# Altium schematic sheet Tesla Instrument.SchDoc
size A4
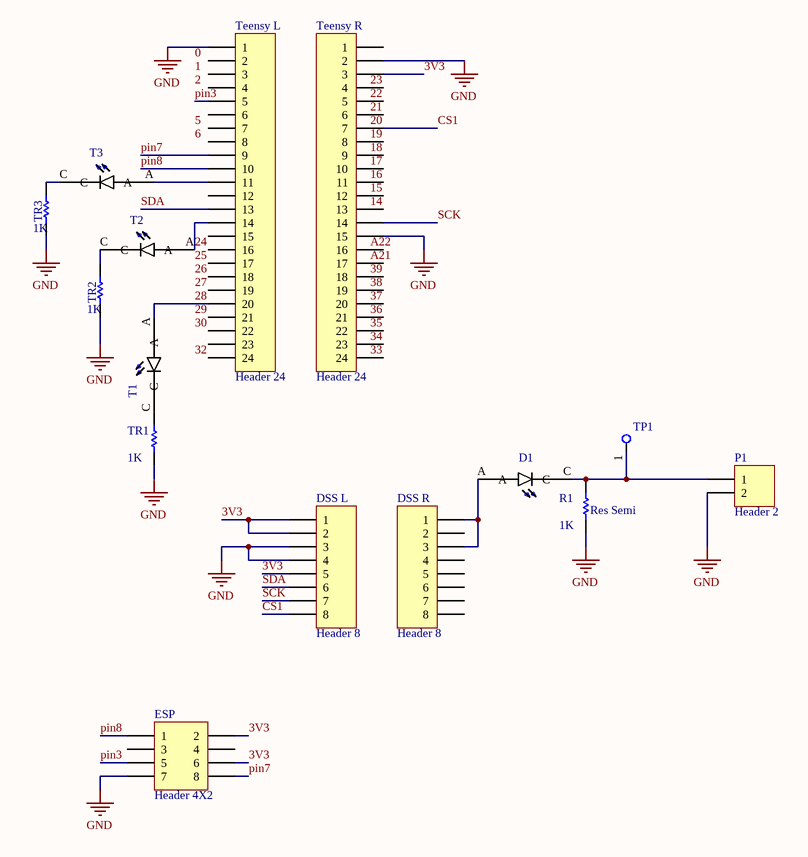
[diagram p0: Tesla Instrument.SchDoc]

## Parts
D1  LTL-1CHYE  [LED_LTL-1CHYE_LTL-1CHYE(Primary)]  (value not drawn)
DSS_L  Header 8  [HDR1X8]
DSS_R  Header 8  [HDR1X8]
ESP  Header 4X2  [HDR2X4]
P1  Header 2  [HDR1X2]
R1  Res Semi  value 1K  [AXIAL-0.5]
T1  LTL-1CHYE  [LED_LTL-1CHYE_LTL-1CHYE(Primary)]  (value not drawn)
T2  LTL-1CHYE  [LED_LTL-1CHYE_LTL-1CHYE(Primary)]  (value not drawn)
T3  LTL-1CHYE  [LED_LTL-1CHYE_LTL-1CHYE(Primary)]  (value not drawn)
Teensy_L  Header 24  [HDR1X24]
Teensy_R  Header 24  [HDR1X24]
TP1  (no value)  [TPCW51D250H460P]
TR1  value 1K  [AXIAL-0.5]
TR2  value 1K  [AXIAL-0.5]
TR3  value 1K  [AXIAL-0.5]

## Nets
GND: DSS_L.3 DSS_L.4 ESP.7 P1.2 R1.1 Teensy_L.1 Teensy_R.2 Teensy_R.15 TR1.1 TR2.1 TR3.1
3V3: DSS_L.1 DSS_L.2 DSS_L.5 ESP.2 ESP.6 Teensy_R.3
24: T2.A Teensy_L.14
28: T1.A Teensy_L.20
CS1: DSS_L.8 Teensy_R.7
pin3: ESP.5 Teensy_L.5
pin7: ESP.8 Teensy_L.9
pin8: ESP.1 Teensy_L.10
SCK: DSS_L.7 Teensy_R.14
SDA: DSS_L.6 Teensy_L.13
NetD1_A: D1.A DSS_R.1 DSS_R.3
NetD1_C: D1.C P1.1 R1.2 TP1.1(TP)
NetT1_C: T1.C TR1.2
NetT2_C: T2.C TR2.2
NetT3_A: T3.A Teensy_L.11
NetT3_C: T3.C TR3.2

Not connected (* = marked no-connect by the designer): DSS_R 2 4 5 6 7 8; ESP 3 4; Teensy_L 2 3 4 6 7 8 12 15 16 17 18 19 21 22 23 24; Teensy_R 1 4 5 6 8 9 10 11 12 13 16 17 18 19 20 21 22 23 24

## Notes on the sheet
- Labels drawn without touching a wire or pin: 0, 1, 2, 5, 6, 14, 15, 16, 17, 18, 19, 20, 21, 22, 23, 25, 26, 27, 29, 30, 32, 33, 34, 35, 36, 37, 38, 39, A21, A22

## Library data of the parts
D1 T1-T3 = LTL-1CHYE: Yellow 3.1 mm 45Â° Tinted Clear 40 mcd 2.1 V LED Through Hole; MF: Lite-On
DSS_L DSS_R = Header 8: Header, 8-Pin
ESP = Header 4X2: Header, 4-Pin, Dual row
P1 = Header 2: Header, 2-Pin
R1 TR1-TR3 = Res Semi: Semiconductor Resistor
Teensy_L Teensy_R = Header 24: Header, 24-Pin
TP1 = 5003: Test Point; Orange; Thru-Hole; Snap-Fit; SilverPlate; 0.040 in. Dia.; 0.300 In.; MF: Keystone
